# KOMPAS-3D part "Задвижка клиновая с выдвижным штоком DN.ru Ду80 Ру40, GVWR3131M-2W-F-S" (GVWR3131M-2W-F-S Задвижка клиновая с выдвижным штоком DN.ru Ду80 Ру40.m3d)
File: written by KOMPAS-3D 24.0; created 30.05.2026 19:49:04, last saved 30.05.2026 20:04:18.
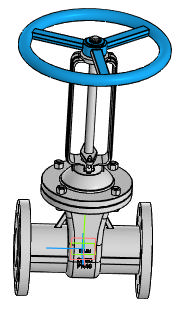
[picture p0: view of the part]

Document properties: Автор: R2D2; Полное имя файла: E:\Работа\Зайцев\GVWR3131M-2W-F-S Задвижка клиновая с выдвижным штоком DN.ru Ду50-100 Ру40\исходные материалы\DN80\DN80\GVWR3131M-2W-F-S Задвижка клиновая с выдвижным штоком DN.ru Ду80 Ру40.m3d

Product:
- Part/product: Задвижка клиновая с выдвижным штоком DN.ru Ду80 Ру40  | designation GVWR3131M-2W-F-S
    Масса: 31
    Раздел спецификации: Прочие изделия
    Примечание: D040-07874

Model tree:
1. Операция без истории:1

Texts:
  GVWR3131M-2W-F-S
